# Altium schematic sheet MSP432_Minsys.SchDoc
size B
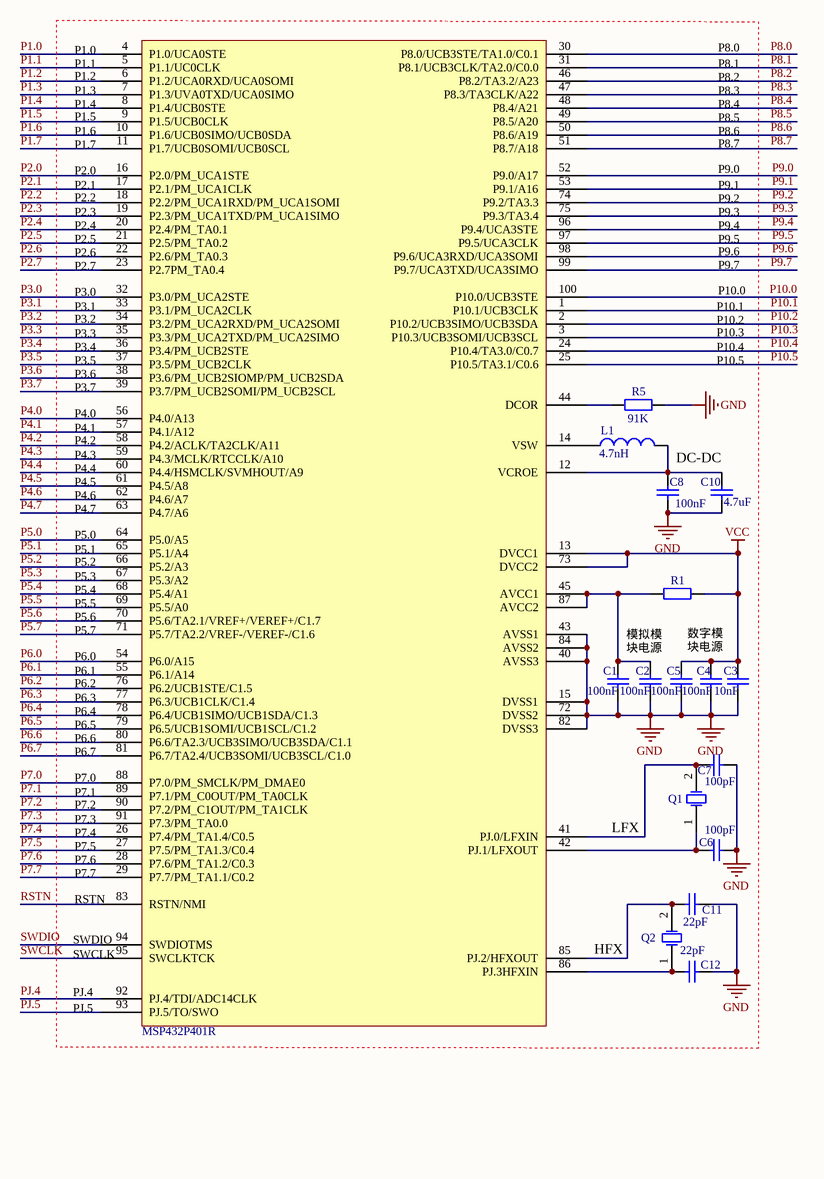
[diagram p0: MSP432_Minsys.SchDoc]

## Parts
*  MSP432P401R  [LQFP100]
C1  value 100nF  [RAD-0.3]  (hidden comment: Cap)
C2  value 100nF  [RAD-0.3]  (hidden comment: Cap)
C3  value 10nF  [RAD-0.3]  (hidden comment: Cap)
C4  value 100nF  [RAD-0.3]  (hidden comment: Cap)
C5  value 100nF  [RAD-0.3]  (hidden comment: Cap)
C6  100pF  [RAD-0.3]
C7  100pF  [RAD-0.3]
C8  value 100nF  [RAD-0.3]  (hidden comment: Cap)
C10  value 4.7uF  [RAD-0.3]  (hidden comment: Cap)
C11  C11: 22pF  [RAD-0.3]  (hidden comment: Cap)
C12  value 22pF  [RAD-0.3]  (hidden comment: Cap)
L1  value 4.7nH  [0402-A]  (hidden comment: Inductor)
Q1  XTAL  [R38]  (value not drawn)
Q2  XTAL  [R38]  (value not drawn)
R1  Res2  [AXIAL-0.4]  (value not drawn)
R5  value 91K  [AXIAL-0.4]  (hidden comment: Res2)

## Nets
GND: *.15(DVSS1) *.40(AVSS3) *.43(AVSS1) *.72(DVSS2) *.82(DVSS3) *.84(AVSS2) C1.1 C2.1 C3.2 C4.2 C5.2 C6.2 C7.2 C8.1 C10.1 C11.2 C12.2 R5.1
VCC: *.13(DVCC1) *.73(DVCC2) C3.1 C4.1 C5.1 R1.2
P1.0: *.4(P1.0/UCA0STE)
P1.1: *.5(P1.1/UC0CLK)
P1.2: *.6(P1.2/UCA0RXD/UCA0SOMI)
P1.3: *.7(P1.3/UVA0TXD/UCA0SIMO)
P1.4: *.8(P1.4/UCB0STE)
P1.5: *.9(P1.5/UCB0CLK)
P1.6: *.10(P1.6/UCB0SIMO/UCB0SDA)
P1.7: *.11(P1.7/UCB0SOMI/UCB0SCL)
P2.0: *.16(P2.0/PM_UCA1STE)
P2.1: *.17(P2.1/PM_UCA1CLK)
P2.2: *.18(P2.2/PM_UCA1RXD/PM_UCA1SOMI)
P2.3: *.19(P2.3/PM_UCA1TXD/PM_UCA1SIMO)
P2.4: *.20(P2.4/PM_TA0.1)
P2.5: *.21(P2.5/PM_TA0.2)
P2.6: *.22(P2.6/PM_TA0.3)
P2.7: *.23(P2.7PM_TA0.4)
P3.0: *.32(P3.0/PM_UCA2STE)
P3.1: *.33(P3.1/PM_UCA2CLK)
P3.2: *.34(P3.2/PM_UCA2RXD/PM_UCA2SOMI)
P3.3: *.35(P3.3/PM_UCA2TXD/PM_UCA2SIMO)
P3.4: *.36(P3.4/PM_UCB2STE)
P3.5: *.37(P3.5/PM_UCB2CLK)
P3.6: *.38(P3.6/PM_UCB2SIOMP/PM_UCB2SDA)
P3.7: *.39(P3.7/PM_UCB2SOMI/PM_UCB2SCL)
P4.0: *.56(P4.0/A13)
P4.1: *.57(P4.1/A12)
P4.2: *.58(P4.2/ACLK/TA2CLK/A11)
P4.3: *.59(P4.3/MCLK/RTCCLK/A10)
P4.4: *.60(P4.4/HSMCLK/SVMHOUT/A9)
P4.5: *.61(P4.5/A8)
P4.6: *.62(P4.6/A7)
P4.7: *.63(P4.7/A6)
P5.0: *.64(P5.0/A5)
P5.1: *.65(P5.1/A4)
P5.2: *.66(P5.2/A3)
P5.3: *.67(P5.3/A2)
P5.4: *.68(P5.4/A1)
P5.5: *.69(P5.5/A0)
P5.6: *.70(P5.6/TA2.1/VREF+/VEREF+/C1.7)
P5.7: *.71(P5.7/TA2.2/VREF-/VEREF-/C1.6)
P6.0: *.54(P6.0/A15)
P6.1: *.55(P6.1/A14)
P6.2: *.76(P6.2/UCB1STE/C1.5)
P6.3: *.77(P6.3/UCB1CLK/C1.4)
P6.4: *.78(P6.4/UCB1SIMO/UCB1SDA/C1.3)
P6.5: *.79(P6.5/UCB1SOMI/UCB1SCL/C1.2)
P6.6: *.80(P6.6/TA2.3/UCB3SIMO/UCB3SDA/C1.1)
P6.7: *.81(P6.7/TA2.4/UCB3SOMI/UCB3SCL/C1.0)
P7.0: *.88(P7.0/PM_SMCLK/PM_DMAE0)
P7.1: *.89(P7.1/PM_C0OUT/PM_TA0CLK)
P7.2: *.90(P7.2/PM_C1OUT/PM_TA1CLK)
P7.3: *.91(P7.3/PM_TA0.0)
P7.4: *.26(P7.4/PM_TA1.4/C0.5)
P7.5: *.27(P7.5/PM_TA1.3/C0.4)
P7.6: *.28(P7.6/PM_TA1.2/C0.3)
P7.7: *.29(P7.7/PM_TA1.1/C0.2)
P8.0: *.30(P8.0/UCB3STE/TA1.0/C0.1)
P8.1: *.31(P8.1/UCB3CLK/TA2.0/C0.0)
P8.2: *.46(P8.2/TA3.2/A23)
P8.3: *.47(P8.3/TA3CLK/A22)
P8.4: *.48(P8.4/A21)
P8.5: *.49(P8.5/A20)
P8.6: *.50(P8.6/A19)
P8.7: *.51(P8.7/A18)
P9.0: *.52(P9.0/A17)
P9.1: *.53(P9.1/A16)
P9.2: *.74(P9.2/TA3.3)
P9.3: *.75(P9.3/TA3.4)
P9.4: *.96(P9.4/UCA3STE)
P9.5: *.97(P9.5/UCA3CLK)
P9.6: *.98(P9.6/UCA3RXD/UCA3SOMI)
P9.7: *.99(P9.7/UCA3TXD/UCA3SIMO)
P10.0: *.100(P10.0/UCB3STE)
P10.1: *.1(P10.1/UCB3CLK)
P10.2: *.2(P10.2/UCB3SIMO/UCB3SDA)
P10.3: *.3(P10.3/UCB3SOMI/UCB3SCL)
P10.4: *.24(P10.4/TA3.0/C0.7)
P10.5: *.25(P10.5/TA3.1/C0.6)
PJ.4: *.92(PJ.4/TDI/ADC14CLK)
PJ.5: *.93(PJ.5/TO/SWO)
RSTN: *.83(RSTN/NMI)
SWCLK: *.95(SWCLKTCK)
SWDIO: *.94(SWDIOTMS)
Net*_12: *.12(VCROE) C8.2 C10.2 L1.2
Net*_14: *.14(VSW) L1.1
Net*_41: *.41(PJ.0/LFXIN) C7.1 Q1.2(OSC2)
Net*_42: *.42(PJ.1/LFXOUT) C6.1 Q1.1(OSC1)
Net*_44: *.44(DCOR) R5.2
Net*_45: *.45(AVCC1) *.87(AVCC2) C1.2 C2.2 R1.1
Net*_85: *.85(PJ.2/HFXOUT) C11.1 Q2.2(OSC2)
Net*_86: *.86(PJ.3HFXIN) C12.1 Q2.1(OSC1)

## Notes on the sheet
- (near *) P1.0
- (near *) P1.1
- P8.0
- P8.1
- (near *) P1.2
- (near *) P1.3
- (near *) P1.4
- (near *) P1.5
- (near *) P1.6
- P8.2
- P8.3
- P8.4
- P8.5
- P8.6
- (near *) P1.7
- (near *) P2.0
- (near *) P2.1
- (near *) P2.2
- P8.7
- P9.0
- P9.1
- P9.2
- (near *) P2.3
- (near *) P2.4
- (near *) P2.5
- (near *) P2.6
- (near *) P2.7
- P9.3
- P9.4
- P9.5
- P9.6
- P9.7
- (near *) P3.0
- (near *) P3.1
- (near *) P3.2
- (near *) P3.3
- P10.1
- P10.2
- P10.3
- P10.0
- (near *) P3.4
- (near *) P3.5
- (near *) P3.6
- (near *) P3.7
- P10.5
- P10.4
- (near *) P4.0
- (near *) P4.1
- (near *) P4.2
- (near *) P4.3
- (near *) P4.4
- DC-DC
- (near *) P4.5
- (near *) P4.6
- (near *) P4.7
- (near *) P5.0
- (near *) P5.1
- (near *) P5.2
- (near *) P5.3
- (near *) P5.4
- (near *) P5.5
- (near *) P5.6
- (near *) P5.7
- (near *) P6.0
- (near *) P6.1
- 模拟模
  块电源
- 数字模
  块电源
- (near *) P6.2
- (near *) P6.3
- (near *) P6.4
- (near *) P6.5
- (near *) P6.6
- (near *) P6.7
- (near *) P7.0
- (near *) P7.1
- (near *) P7.2
- (near *) P7.3
- (near *) P7.4
- (near *) P7.5
- (near *) P7.6
- (near *) P7.7
- LFX
- (near *) SWDIO
- (near *) RSTN
- (near *) SWCLK
- (near *) PJ.4
- (near *) PJ.5
- HFX

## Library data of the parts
C1-C8 C10-C12 = Cap: Capacitor
L1 = Inductor: Code_IEC: 1005
Q1 Q2 = XTAL: Crystal Oscillator
R1 = Res2: Resistor; Value: 1K
R5 = Res2: Resistor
